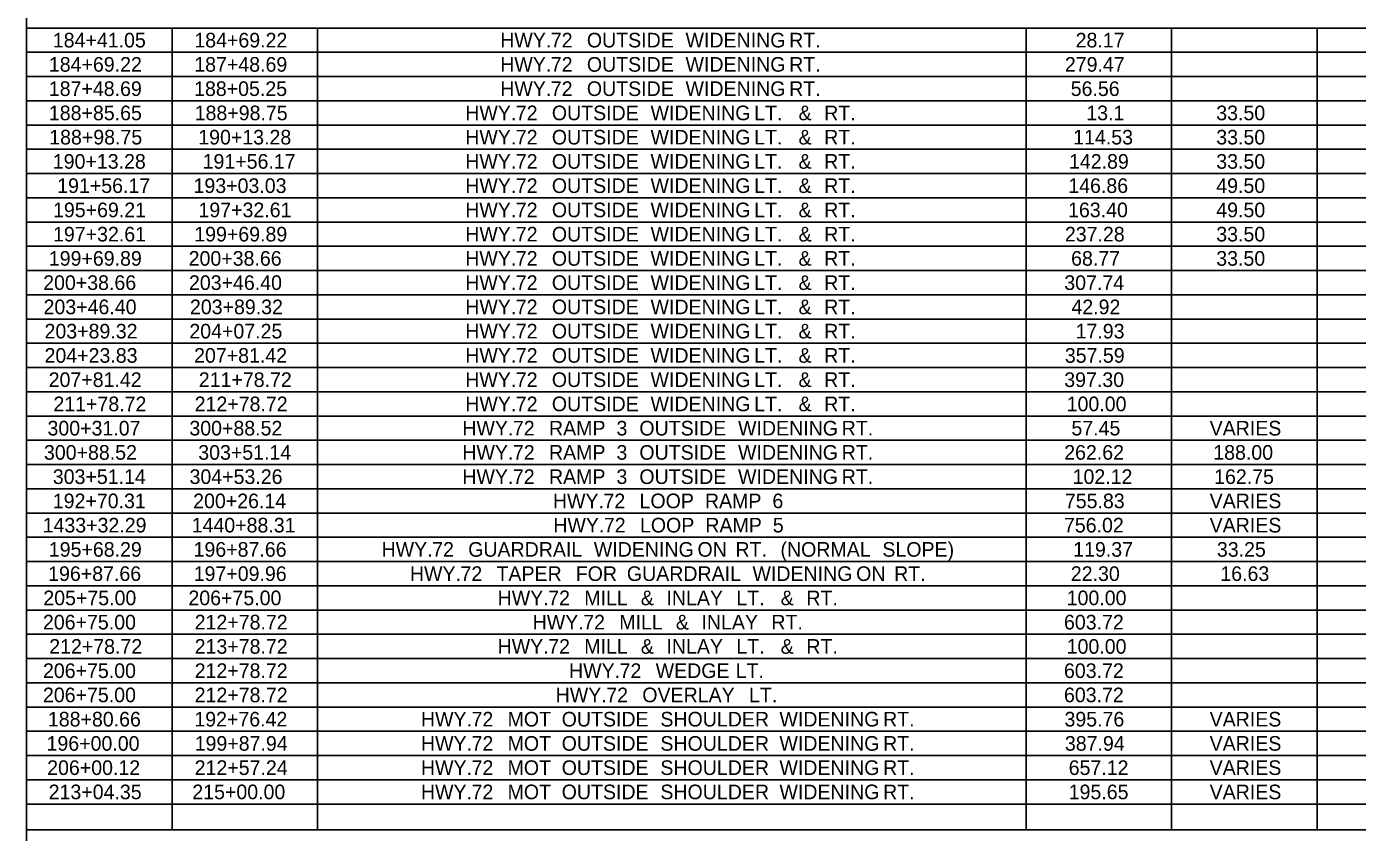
# Model space of a CAD drawing. Extents: x 1226567 to 1228151, y 151309 to 152305.
# Drawn here: x 1226566.8 to 1226930.3, y 151833.3 to 152053.3 of the extents above; entities that cross this region are included whole.
import ezdxf

# ---------------------------------------------------------------- set-up
doc = ezdxf.new("R2010")
doc.units = 0
doc.layers.add('R_Dimension', color=7, linetype='Continuous')

msp = doc.modelspace()

# ---------------------------------------------------------------- linework, layer by layer
at = {"layer": 'R_Dimension'}
for p, q in [((1226566.84, 151664.64), (1226566.84, 152254.68)), ((1226566.84, 152052.93), (1228150.79, 152052.93)), ((1226606.57, 151834.06), (1226606.57, 152052.93)), ((1226646.29, 151834.06), (1226646.29, 152052.93)), ((1226839.86, 151834.06), (1226839.86, 152052.93)), ((1226879.58, 151834.06), (1226879.58, 152052.93)), ((1226919.31, 151834.06), (1226919.31, 152052.93)), ((1226566.84, 152046.31), (1228150.79, 152046.31)), ((1226566.84, 152039.69), (1228150.79, 152039.69)), ((1226566.84, 152033.07), (1228150.79, 152033.07)), ((1226566.84, 152026.45), (1228150.79, 152026.45)), ((1226566.84, 152019.83), (1228150.79, 152019.83)), ((1226566.84, 152013.21), (1228150.79, 152013.21)), ((1226566.84, 152006.59), (1228150.79, 152006.59)), ((1226566.84, 151999.97), (1228150.79, 151999.97)), ((1226566.84, 151993.35), (1228150.79, 151993.35)), ((1226566.84, 151986.73), (1228150.79, 151986.73)), ((1226566.84, 151980.1), (1228150.79, 151980.1)), ((1226566.84, 151973.48), (1228150.79, 151973.48)), ((1226566.84, 151966.86), (1228150.79, 151966.86)), ((1226566.84, 151960.24), (1228150.79, 151960.24)), ((1226566.84, 151953.62), (1228150.79, 151953.62)), ((1226566.84, 151947), (1228150.79, 151947)), ((1226566.84, 151940.38), (1228150.79, 151940.38)), ((1226566.84, 151933.76), (1228150.79, 151933.76)), ((1226566.84, 151927.14), (1228150.79, 151927.14)), ((1226566.84, 151920.52), (1228150.79, 151920.52)), ((1226566.84, 151913.9), (1228150.79, 151913.9)), ((1226566.84, 151907.27), (1228150.79, 151907.27)), ((1226566.84, 151900.65), (1228150.79, 151900.65)), ((1226566.84, 151894.03), (1228150.79, 151894.03)), ((1226566.84, 151887.41), (1228150.79, 151887.41)), ((1226566.84, 151880.79), (1228150.79, 151880.79)), ((1226566.84, 151874.17), (1228150.79, 151874.17)), ((1226566.84, 151867.55), (1228150.79, 151867.55)), ((1226566.84, 151860.93), (1228150.79, 151860.93)), ((1226566.84, 151854.31), (1228150.79, 151854.31)), ((1226566.84, 151847.69), (1228150.79, 151847.69)), ((1226566.84, 151841.07), (1228150.79, 151841.07)), ((1226566.84, 151834.06), (1228150.79, 151834.06))]:
    msp.add_line(p, q, dxfattribs=at)

# ---------------------------------------------------------------- texts
for s, p in [('184+41.05', (1226574, 152047.63)), ('184+69.22', (1226612.66, 152047.63)), ('HWY.', (1226696.21, 152047.63)), (' 72', (1226708.54, 152047.63)), (' OUTSIDE', (1226718.39, 152047.63)), (' WIDENING', (1226745.34, 152047.63)), (' RT.', (1226773.65, 152047.63)), ('28.17', (1226853.37, 152047.63)), ('184+69.22', (1226572.93, 152041.01)), ('187+48.69', (1226612.64, 152041.01)), ('HWY.', (1226696.21, 152041.01)), (' 72', (1226708.54, 152041.01)), (' OUTSIDE', (1226718.39, 152041.01)), (' WIDENING', (1226745.34, 152041.01)), (' RT.', (1226773.65, 152041.01)), ('279.47', (1226850.44, 152041.01)), ('187+48.69', (1226572.91, 152034.38)), ('188+05.25', (1226612.59, 152034.38)), ('HWY.', (1226696.21, 152034.38)), (' 72', (1226708.54, 152034.38)), (' OUTSIDE', (1226718.39, 152034.38)), (' WIDENING', (1226745.34, 152034.38)), (' RT.', (1226773.65, 152034.38)), ('56.56', (1226852.03, 152034.38)), ('188+85.65', (1226572.93, 152027.76)), ('188+98.75', (1226612.75, 152027.76)), ('HWY.', (1226686.65, 152027.76)), (' 72', (1226698.98, 152027.76)), (' OUTSIDE', (1226708.82, 152027.76)), (' WIDENING', (1226735.78, 152027.76)), (' LT.', (1226764.09, 152027.76)), (' &', (1226776.2, 152027.76)), (' RT.', (1226783.21, 152027.76)), ('13.1', (1226856.29, 152027.76)), ('33.50', (1226891.79, 152027.76)), ('188+98.75', (1226573.02, 152021.14)), ('190+13.28', (1226613.73, 152021.14)), ('HWY.', (1226686.65, 152021.14)), (' 72', (1226698.98, 152021.14)), (' OUTSIDE', (1226708.82, 152021.14)), (' WIDENING', (1226735.78, 152021.14)), (' LT.', (1226764.09, 152021.14)), (' &', (1226776.2, 152021.14)), (' RT.', (1226783.21, 152021.14)), ('114.53', (1226852.71, 152021.14)), ('33.50', (1226891.79, 152021.14)), ('190+13.28', (1226574, 152014.52)), ('191+56.17', (1226614.92, 152014.52)), ('HWY.', (1226686.65, 152014.52)), (' 72', (1226698.98, 152014.52)), (' OUTSIDE', (1226708.82, 152014.52)), (' WIDENING', (1226735.78, 152014.52)), (' LT.', (1226764.09, 152014.52)), (' &', (1226776.2, 152014.52)), (' RT.', (1226783.21, 152014.52)), ('142.89', (1226851.56, 152014.52)), ('33.50', (1226891.79, 152014.52)), ('191+56.17', (1226575.2, 152007.9)), ('193+03.03', (1226612.44, 152007.9)), ('HWY.', (1226686.65, 152007.9)), (' 72', (1226698.98, 152007.9)), (' OUTSIDE', (1226708.82, 152007.9)), (' WIDENING', (1226735.78, 152007.9)), (' LT.', (1226764.09, 152007.9)), (' &', (1226776.2, 152007.9)), (' RT.', (1226783.21, 152007.9)), ('146.86', (1226851.37, 152007.9)), ('49.50', (1226891.79, 152007.9)), ('195+69.21', (1226574.06, 152001.28)), ('197+32.61', (1226613.79, 152001.28)), ('HWY.', (1226686.65, 152001.28)), (' 72', (1226698.98, 152001.28)), (' OUTSIDE', (1226708.82, 152001.28)), (' WIDENING', (1226735.78, 152001.28)), (' LT.', (1226764.09, 152001.28)), (' &', (1226776.2, 152001.28)), (' RT.', (1226783.21, 152001.28)), ('163.40', (1226851.31, 152001.28)), ('49.50', (1226891.79, 152001.28)), ('197+32.61', (1226574.06, 151994.66)), ('199+69.89', (1226612.64, 151994.66)), ('HWY.', (1226686.65, 151994.66)), (' 72', (1226698.98, 151994.66)), (' OUTSIDE', (1226708.82, 151994.66)), (' WIDENING', (1226735.78, 151994.66)), (' LT.', (1226764.09, 151994.66)), (' &', (1226776.2, 151994.66)), (' RT.', (1226783.21, 151994.66)), ('237.28', (1226850.44, 151994.66)), ('33.50', (1226891.79, 151994.66)), ('199+69.89', (1226572.91, 151988.04)), ('200+38.66', (1226611.1, 151988.04)), ('HWY.', (1226686.65, 151988.04)), (' 72', (1226698.98, 151988.04)), (' OUTSIDE', (1226708.82, 151988.04)), (' WIDENING', (1226735.78, 151988.04)), (' LT.', (1226764.09, 151988.04)), (' &', (1226776.2, 151988.04)), (' RT.', (1226783.21, 151988.04)), ('68.77', (1226852.14, 151988.04)), ('33.50', (1226891.79, 151988.04)), ('200+38.66', (1226571.37, 151981.42)), ('203+46.40', (1226611.19, 151981.42)), ('HWY.', (1226686.65, 151981.42)), (' 72', (1226698.98, 151981.42)), (' OUTSIDE', (1226708.82, 151981.42)), (' WIDENING', (1226735.78, 151981.42)), (' LT.', (1226764.09, 151981.42)), (' &', (1226776.2, 151981.42)), (' RT.', (1226783.21, 151981.42)), ('307.74', (1226850.28, 151981.42)), ('203+46.40', (1226571.47, 151974.8)), ('203+89.32', (1226611.46, 151974.8)), ('HWY.', (1226686.65, 151974.8)), (' 72', (1226698.98, 151974.8)), (' OUTSIDE', (1226708.82, 151974.8)), (' WIDENING', (1226735.78, 151974.8)), (' LT.', (1226764.09, 151974.8)), (' &', (1226776.2, 151974.8)), (' RT.', (1226783.21, 151974.8)), ('42.92', (1226852.23, 151974.8)), ('203+89.32', (1226571.74, 151968.18)), ('204+07.25', (1226611.3, 151968.18)), ('HWY.', (1226686.65, 151968.18)), (' 72', (1226698.98, 151968.18)), (' OUTSIDE', (1226708.82, 151968.18)), (' WIDENING', (1226735.78, 151968.18)), (' LT.', (1226764.09, 151968.18)), (' &', (1226776.2, 151968.18)), (' RT.', (1226783.21, 151968.18)), ('17.93', (1226853.37, 151968.18)), ('204+23.83', (1226571.74, 151961.55)), ('207+81.42', (1226612.59, 151961.55)), ('HWY.', (1226686.65, 151961.55)), (' 72', (1226698.98, 151961.55)), (' OUTSIDE', (1226708.82, 151961.55)), (' WIDENING', (1226735.78, 151961.55)), (' LT.', (1226764.09, 151961.55)), (' &', (1226776.2, 151961.55)), (' RT.', (1226783.21, 151961.55)), ('357.59', (1226850.43, 151961.55)), ('207+81.42', (1226572.87, 151954.93)), ('211+78.72', (1226613.88, 151954.93)), ('HWY.', (1226686.65, 151954.93)), (' 72', (1226698.98, 151954.93)), (' OUTSIDE', (1226708.82, 151954.93)), (' WIDENING', (1226735.78, 151954.93)), (' LT.', (1226764.09, 151954.93)), (' &', (1226776.2, 151954.93)), (' RT.', (1226783.21, 151954.93)), ('397.30', (1226850.27, 151954.93)), ('211+78.72', (1226574.16, 151948.31)), ('212+78.72', (1226612.75, 151948.31)), ('HWY.', (1226686.65, 151948.31)), (' 72', (1226698.98, 151948.31)), (' OUTSIDE', (1226708.82, 151948.31)), (' WIDENING', (1226735.78, 151948.31)), (' LT.', (1226764.09, 151948.31)), (' &', (1226776.2, 151948.31)), (' RT.', (1226783.21, 151948.31)), ('100.00', (1226850.93, 151948.31)), ('300+31.07', (1226572.55, 151941.69)), ('300+88.52', (1226611.3, 151941.69)), ('HWY.', (1226685.86, 151941.69)), (' 72', (1226698.19, 151941.69)), (' RAMP', (1226708.04, 151941.69)), (' 3', (1226726.47, 151941.69)), (' OUTSIDE', (1226732.73, 151941.69)), (' WIDENING', (1226759.68, 151941.69)), (' RT.', (1226787.99, 151941.69)), ('57.45', (1226852.23, 151941.69)), ('VARIES', (1226889.98, 151941.69)), ('300+88.52', (1226571.58, 151935.07)), ('303+51.14', (1226613.73, 151935.07)), ('HWY.', (1226685.86, 151935.07)), (' 72', (1226698.19, 151935.07)), (' RAMP', (1226708.04, 151935.07)), (' 3', (1226726.47, 151935.07)), (' OUTSIDE', (1226732.73, 151935.07)), (' WIDENING', (1226759.68, 151935.07)), (' RT.', (1226787.99, 151935.07)), ('262.62', (1226850.25, 151935.07)), ('188.00', (1226890.97, 151935.07)), ('303+51.14', (1226574, 151928.45)), ('304+53.26', (1226611.35, 151928.45)), ('HWY.', (1226685.86, 151928.45)), (' 72', (1226698.19, 151928.45)), (' RAMP', (1226708.04, 151928.45)), (' 3', (1226726.47, 151928.45)), (' OUTSIDE', (1226732.73, 151928.45)), (' WIDENING', (1226759.68, 151928.45)), (' RT.', (1226787.99, 151928.45)), ('102.12', (1226852.55, 151928.45)), ('162.75', (1226891.2, 151928.45)), ('192+70.31', (1226574, 151921.83)), ('200+26.14', (1226612.34, 151921.83)), ('HWY.', (1226710.6, 151921.83)), (' 72', (1226722.93, 151921.83)), (' LOOP', (1226732.78, 151921.83)), (' RAMP', (1226750.64, 151921.83)), (' 6', (1226769.07, 151921.83)), ('755.83', (1226850.44, 151921.83)), ('VARIES', (1226889.98, 151921.83)), ('1433+32.29', (1226571.22, 151915.21)), ('1440+88.31', (1226611.93, 151915.21)), ('HWY.', (1226710.71, 151915.21)), (' 72', (1226723.04, 151915.21)), (' LOOP', (1226732.89, 151915.21)), (' RAMP', (1226750.75, 151915.21)), (' 5', (1226769.18, 151915.21)), ('756.02', (1226850.19, 151915.21)), ('VARIES', (1226889.98, 151915.21)), ('195+68.29', (1226572.91, 151908.59)), ('196+87.66', (1226612.45, 151908.59)), ('HWY.', (1226663.8, 151908.59)), (' 72', (1226676.13, 151908.59)), (' GUARDRAIL', (1226685.97, 151908.59)), (' WIDENING', (1226720.29, 151908.59)), (' ON', (1226748.6, 151908.59)), (' RT.', (1226758.98, 151908.59)), (' (NORMAL', (1226771.27, 151908.59)), (' SLOPE)', (1226799.11, 151908.59)), ('119.37', (1226852.71, 151908.59)), ('33.25', (1226891.96, 151908.59)), ('196+87.66', (1226572.73, 151901.97)), ('197+09.96', (1226612.48, 151901.97)), ('HWY.', (1226671.54, 151901.97)), (' 72', (1226683.87, 151901.97)), (' TAPER', (1226693.71, 151901.97)), (' FOR', (1226715.35, 151901.97)), (' GUARDRAIL', (1226729.32, 151901.97)), (' WIDENING', (1226763.63, 151901.97)), (' ON', (1226791.94, 151901.97)), (' RT.', (1226802.32, 151901.97)), ('22.30', (1226852.06, 151901.97)), ('16.63', (1226892.9, 151901.97)), ('205+75.00', (1226571.41, 151895.35)), ('206+75.00', (1226611.04, 151895.35)), ('HWY.', (1226695.5, 151895.35)), (' 72', (1226707.83, 151895.35)), (' MILL', (1226717.68, 151895.35)), (' &', (1226733.12, 151895.35)), (' INLAY', (1226740.14, 151895.35)), (' LT.', (1226759.23, 151895.35)), (' &', (1226771.34, 151895.35)), (' RT.', (1226778.35, 151895.35)), ('100.00', (1226850.93, 151895.35)), ('206+75.00', (1226571.31, 151888.73)), ('212+78.72', (1226612.75, 151888.73)), ('HWY.', (1226705.07, 151888.73)), (' 72', (1226717.39, 151888.73)), (' MILL', (1226727.24, 151888.73)), (' &', (1226742.68, 151888.73)), (' INLAY', (1226749.7, 151888.73)), (' RT.', (1226768.79, 151888.73)), ('603.72', (1226850.19, 151888.73)), ('212+78.72', (1226573.02, 151882.1)), ('213+78.72', (1226612.75, 151882.1)), ('HWY.', (1226695.5, 151882.1)), (' 72', (1226707.83, 151882.1)), (' MILL', (1226717.68, 151882.1)), (' &', (1226733.12, 151882.1)), (' INLAY', (1226740.14, 151882.1)), (' LT.', (1226759.23, 151882.1)), (' &', (1226771.34, 151882.1)), (' RT.', (1226778.35, 151882.1)), ('100.00', (1226850.93, 151882.1)), ('206+75.00', (1226571.31, 151875.48)), ('212+78.72', (1226612.75, 151875.48)), ('HWY.', (1226715, 151875.48)), (' 72', (1226727.33, 151875.48)), (' WEDGE', (1226737.18, 151875.48)), (' LT.', (1226759.04, 151875.48)), ('603.72', (1226850.19, 151875.48)), ('206+75.00', (1226571.31, 151868.86)), ('212+78.72', (1226612.75, 151868.86)), ('HWY.', (1226711.36, 151868.86)), (' 72', (1226723.69, 151868.86)), (' OVERLAY', (1226733.53, 151868.86)), (' LT.', (1226762.69, 151868.86)), ('603.72', (1226850.19, 151868.86)), ('188+80.66', (1226572.66, 151862.24)), ('192+76.42', (1226612.66, 151862.24)), ('HWY.', (1226674.56, 151862.24)), (' 72', (1226686.89, 151862.24)), (' MOT', (1226696.73, 151862.24)), (' OUTSIDE', (1226711.51, 151862.24)), (' SHOULDER', (1226738.47, 151862.24)), (' WIDENING', (1226770.99, 151862.24)), (' RT.', (1226799.3, 151862.24)), ('395.76', (1226850.33, 151862.24)), ('VARIES', (1226889.98, 151862.24)), ('196+00.00', (1226572.29, 151855.62)), ('199+87.94', (1226612.75, 151855.62)), ('HWY.', (1226674.56, 151855.62)), (' 72', (1226686.89, 151855.62)), (' MOT', (1226696.73, 151855.62)), (' OUTSIDE', (1226711.51, 151855.62)), (' SHOULDER', (1226738.47, 151855.62)), (' WIDENING', (1226770.99, 151855.62)), (' RT.', (1226799.3, 151855.62)), ('387.94', (1226850.44, 151855.62)), ('VARIES', (1226889.98, 151855.62)), ('206+00.12', (1226572.46, 151849)), ('212+57.24', (1226612.75, 151849)), ('HWY.', (1226674.56, 151849)), (' 72', (1226686.89, 151849)), (' MOT', (1226696.73, 151849)), (' OUTSIDE', (1226711.51, 151849)), (' SHOULDER', (1226738.47, 151849)), (' WIDENING', (1226770.99, 151849)), (' RT.', (1226799.3, 151849)), ('657.12', (1226851.48, 151849)), ('VARIES', (1226889.98, 151849)), ('213+04.35', (1226572.87, 151842.38)), ('215+00.00', (1226612.11, 151842.38)), ('HWY.', (1226674.56, 151842.38)), (' 72', (1226686.89, 151842.38)), (' MOT', (1226696.73, 151842.38)), (' OUTSIDE', (1226711.51, 151842.38)), (' SHOULDER', (1226738.47, 151842.38)), (' WIDENING', (1226770.99, 151842.38)), (' RT.', (1226799.3, 151842.38)), ('195.65', (1226851.48, 151842.38)), ('VARIES', (1226889.98, 151842.38))]:
    msp.add_text(s, height=3.994, dxfattribs=at).set_placement(p)

doc.saveas('drawing.dxf')
